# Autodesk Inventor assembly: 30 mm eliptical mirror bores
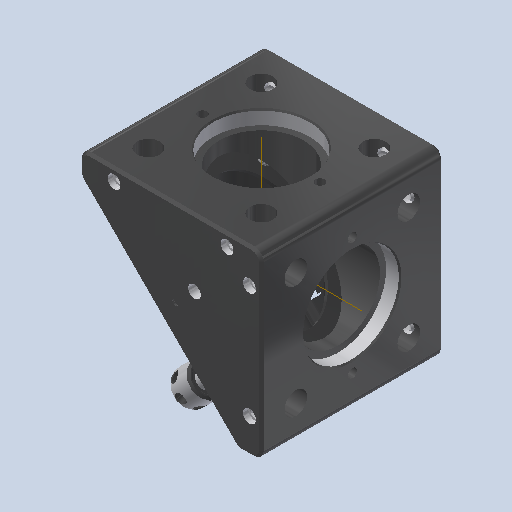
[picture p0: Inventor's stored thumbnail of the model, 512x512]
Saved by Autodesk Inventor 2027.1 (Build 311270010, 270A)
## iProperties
Created: 2017-01
Part Number: 30 mm eliptical mirror bores
Document SubType Name: Assembly
Designer: Radek
Author: Radek
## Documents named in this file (3)
- C:\Users\dunge\OneDrive\Documents\Inventor\Inventor\Inventor\simplified-drawings\imports\30 mm eliptical mirror bores.iam
- C:\Users\dunge\OneDrive\Documents\Inventor\Inventor\Inventor\1p2p\imported\rotation mounts\KCB1EC_M-Solidworks.ipt
- C:\Users\Radek\Documents\Repozytoria\Inventor\Mircroscopes\1p2p microscope\Workspaces\Workspace\imported\mirrors\BBE1-E03-Solidworks.ipt
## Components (2 placed, 2 different names)
1. KCB1EC_M-Solidworks:1 — Mate:1, Angle:1, Tangent:1, Mate:2, Mate:3
2. BBE1-E03-Solidworks:1 — Mate:1, Angle:1, Tangent:1
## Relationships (5: Mate 3, Angle 1, Tangent 1)
- Mate:1: KCB1EC_M-Solidworks:1 ↔ BBE1-E03-Solidworks:1
- Angle:1: KCB1EC_M-Solidworks:1 ↔ BBE1-E03-Solidworks:1
- Tangent:1: KCB1EC_M-Solidworks:1 ↔ BBE1-E03-Solidworks:1
- Mate:2: KCB1EC_M-Solidworks:1
- Mate:3: KCB1EC_M-Solidworks:1
